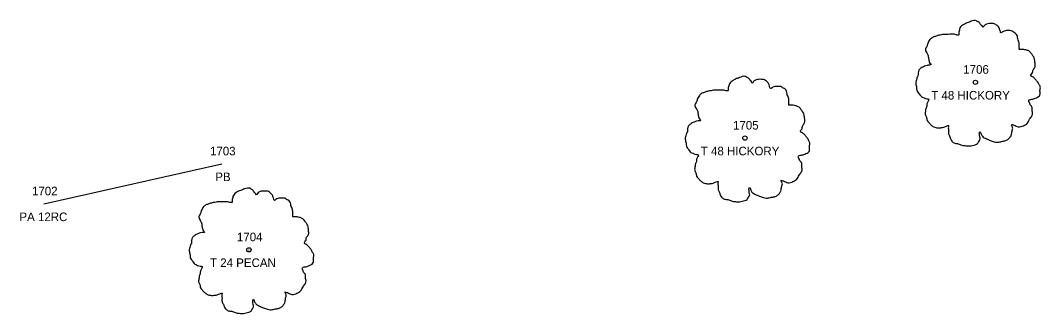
# Model space of a CAD drawing. Extents: x 1965822 to 1970313, y 1117097 to 1118160.
# Drawn here: x 1966536.2 to 1966654.8, y 1117362.7 to 1117396.8 of the extents above; entities that cross this region are included whole.
import ezdxf

# ---------------------------------------------------------------- set-up
doc = ezdxf.new("R2010")
doc.units = 0
for name, color, linetype in [('RD_EX_DR_Pipe', 7, 'Continuous'), ('RD_EX_DR_Pipe_txCode', 7, 'Continuous'), ('RD_EX_VEG', 7, 'Continuous'), ('RD_EX_VEG_txCode', 7, 'Continuous'), ('RD_SMD_Locator', 7, 'Continuous')]:
    doc.layers.add(name, color=color, linetype=linetype)

msp = doc.modelspace()

# ---------------------------------------------------------------- linework, layer by layer
at = {"layer": 'RD_EX_DR_Pipe'}
msp.add_line((1966538.93, 1117375.41), (1966559.64, 1117380.06), dxfattribs=at)
at = {"layer": 'RD_EX_VEG'}
for centre, radius in [((1966647.25, 1117389.55), 0.25), ((1966647.24, 1117389.53), 0.0001), ((1966620.45, 1117383.06), 0.25), ((1966620.44, 1117383.04), 0.0001), ((1966562.77, 1117370.07), 0.25), ((1966562.75, 1117370.05), 0.0001)]:
    msp.add_circle(centre, radius, dxfattribs=at)
for points in [[(1966647.38, 1117396.72), (1966647.08, 1117396.75), (1966646.76, 1117396.65), (1966646.51, 1117396.55), (1966646.28, 1117396.47), (1966646.06, 1117396.37), (1966645.76, 1117396.2), (1966645.53, 1117396), (1966645.41, 1117395.75), (1966645.36, 1117395.52), (1966645.31, 1117395.25), (1966645.31, 1117395.07), (1966645.18, 1117395.05), (1966645.03, 1117395.07), (1966644.78, 1117395.15), (1966644.53, 1117395.15), (1966644.28, 1117395.15), (1966643.93, 1117395.12), (1966643.58, 1117395.12), (1966643.31, 1117395.07), (1966642.98, 1117395.02), (1966642.61, 1117394.9), (1966642.26, 1117394.77), (1966641.96, 1117394.52), (1966641.71, 1117394.05), (1966641.59, 1117393.7), (1966641.44, 1117393.45), (1966641.59, 1117393), (1966641.76, 1117392.65), (1966641.79, 1117392.45), (1966641.86, 1117392.02), (1966641.96, 1117391.8), (1966642.08, 1117391.6), (1966642.01, 1117391.57), (1966641.64, 1117391.52), (1966641.34, 1117391.42), (1966640.91, 1117391.2), (1966640.69, 1117390.97), (1966640.59, 1117390.65), (1966640.56, 1117390.3), (1966640.46, 1117390.1), (1966640.39, 1117389.82), (1966640.36, 1117389.75), (1966640.31, 1117389.42), (1966640.41, 1117388.97), (1966640.44, 1117388.62), (1966640.56, 1117388.4), (1966640.71, 1117388.22), (1966640.89, 1117387.97), (1966641.29, 1117387.75), (1966641.61, 1117387.65), (1966641.81, 1117387.63), (1966641.64, 1117387.13), (1966641.59, 1117386.78), (1966641.46, 1117386.38), (1966641.46, 1117386.3), (1966641.41, 1117385.83), (1966641.56, 1117385.5), (1966641.64, 1117385.13), (1966641.81, 1117384.9), (1966642.08, 1117384.6), (1966642.41, 1117384.38), (1966642.91, 1117384.25), (1966643.31, 1117384.28), (1966643.88, 1117384.45), (1966644.13, 1117384.53), (1966644.11, 1117384.35), (1966644.13, 1117383.98), (1966644.13, 1117383.55), (1966644.28, 1117383.23), (1966644.38, 1117382.95), (1966644.53, 1117382.7), (1966644.86, 1117382.48), (1966645.26, 1117382.4), (1966645.68, 1117382.25), (1966646.13, 1117382.18), (1966646.63, 1117382.15), (1966647.23, 1117382.3), (1966647.51, 1117382.43), (1966647.61, 1117382.6), (1966647.81, 1117382.98), (1966647.76, 1117383.2), (1966647.78, 1117383.8), (1966647.88, 1117383.63), (1966648.06, 1117383.28), (1966648.56, 1117382.98), (1966648.96, 1117382.8), (1966649.43, 1117382.65), (1966649.73, 1117382.58), (1966650.21, 1117382.65), (1966650.58, 1117382.73), (1966650.96, 1117382.85), (1966651.26, 1117383.13), (1966651.43, 1117383.4), (1966651.48, 1117383.68), (1966651.56, 1117384.05), (1966651.61, 1117384.23)], [(1966651.61, 1117384.23), (1966651.53, 1117384.4), (1966651.48, 1117384.65), (1966651.56, 1117384.63), (1966651.73, 1117384.58), (1966652.01, 1117384.45), (1966652.23, 1117384.38), (1966652.56, 1117384.4), (1966652.83, 1117384.5), (1966653.28, 1117384.78), (1966653.55, 1117385.25), (1966653.83, 1117385.65), (1966653.9, 1117385.98), (1966653.85, 1117386.2), (1966653.83, 1117386.7), (1966653.63, 1117386.95), (1966653.58, 1117387.08), (1966653.48, 1117387.48), (1966653.55, 1117387.53), (1966653.83, 1117387.58), (1966654.2, 1117387.7), (1966654.48, 1117387.82), (1966654.7, 1117388), (1966654.78, 1117388.22), (1966654.75, 1117388.62), (1966654.8, 1117389.02), (1966654.73, 1117389.17), (1966654.63, 1117389.32), (1966654.55, 1117389.52), (1966654.4, 1117389.67), (1966654.3, 1117389.82), (1966654.2, 1117389.92), (1966654.08, 1117390.07), (1966653.9, 1117390.2), (1966653.75, 1117390.25), (1966653.7, 1117390.4), (1966653.85, 1117390.6), (1966653.9, 1117390.7), (1966653.93, 1117390.92), (1966654.15, 1117391.27), (1966654.2, 1117391.67), (1966654.15, 1117392.1), (1966654.1, 1117392.37), (1966653.95, 1117392.65), (1966653.75, 1117392.9), (1966653.63, 1117393.07), (1966653.45, 1117393.2), (1966653.13, 1117393.32), (1966652.88, 1117393.37), (1966652.53, 1117393.37), (1966652.33, 1117393.42), (1966652.36, 1117393.47), (1966652.36, 1117393.62), (1966652.36, 1117393.9), (1966652.28, 1117394.35), (1966652.13, 1117394.85), (1966652.13, 1117394.87), (1966652.03, 1117395.12), (1966651.81, 1117395.32), (1966651.63, 1117395.42), (1966651.43, 1117395.55), (1966651.18, 1117395.57), (1966650.88, 1117395.57), (1966650.61, 1117395.52), (1966650.41, 1117395.42), (1966650.23, 1117395.3), (1966650.16, 1117395.45), (1966650.06, 1117395.75), (1966650.01, 1117395.9), (1966649.86, 1117396.07), (1966649.63, 1117396.27), (1966649.18, 1117396.4), (1966648.56, 1117396.32), (1966648.26, 1117396.12), (1966648.11, 1117395.95), (1966648.06, 1117396.07), (1966647.86, 1117396.27), (1966647.76, 1117396.45), (1966647.58, 1117396.57), (1966647.43, 1117396.67), (1966647.33, 1117396.72)], [(1966620.59, 1117390.23), (1966620.29, 1117390.25), (1966619.96, 1117390.15), (1966619.71, 1117390.05), (1966619.49, 1117389.98), (1966619.26, 1117389.88), (1966618.96, 1117389.7), (1966618.74, 1117389.5), (1966618.61, 1117389.25), (1966618.56, 1117389.03), (1966618.51, 1117388.75), (1966618.51, 1117388.58), (1966618.39, 1117388.55), (1966618.24, 1117388.58), (1966617.99, 1117388.65), (1966617.74, 1117388.65), (1966617.49, 1117388.65), (1966617.14, 1117388.63), (1966616.79, 1117388.63), (1966616.51, 1117388.58), (1966616.19, 1117388.53), (1966615.81, 1117388.4), (1966615.46, 1117388.28), (1966615.16, 1117388.03), (1966614.91, 1117387.55), (1966614.79, 1117387.2), (1966614.64, 1117386.95), (1966614.79, 1117386.5), (1966614.96, 1117386.15), (1966614.99, 1117385.95), (1966615.06, 1117385.53), (1966615.16, 1117385.3), (1966615.29, 1117385.1), (1966615.21, 1117385.08), (1966614.84, 1117385.03), (1966614.54, 1117384.93), (1966614.11, 1117384.7), (1966613.89, 1117384.48), (1966613.79, 1117384.15), (1966613.76, 1117383.8), (1966613.66, 1117383.6), (1966613.59, 1117383.33), (1966613.56, 1117383.25), (1966613.51, 1117382.93), (1966613.61, 1117382.48), (1966613.64, 1117382.13), (1966613.76, 1117381.91), (1966613.91, 1117381.73), (1966614.09, 1117381.48), (1966614.49, 1117381.26), (1966614.81, 1117381.16), (1966615.01, 1117381.13), (1966614.84, 1117380.63), (1966614.79, 1117380.28), (1966614.66, 1117379.88), (1966614.66, 1117379.81), (1966614.61, 1117379.33), (1966614.76, 1117379.01), (1966614.84, 1117378.63), (1966615.01, 1117378.41), (1966615.29, 1117378.11), (1966615.61, 1117377.88), (1966616.11, 1117377.76), (1966616.51, 1117377.78), (1966617.09, 1117377.96), (1966617.34, 1117378.03), (1966617.31, 1117377.86), (1966617.34, 1117377.48), (1966617.34, 1117377.06), (1966617.49, 1117376.73), (1966617.59, 1117376.46), (1966617.74, 1117376.21), (1966618.06, 1117375.98), (1966618.46, 1117375.91), (1966618.89, 1117375.76), (1966619.34, 1117375.68), (1966619.84, 1117375.66), (1966620.44, 1117375.81), (1966620.71, 1117375.93), (1966620.81, 1117376.11), (1966621.01, 1117376.48), (1966620.96, 1117376.71), (1966620.99, 1117377.31), (1966621.09, 1117377.13), (1966621.26, 1117376.78), (1966621.76, 1117376.48), (1966622.16, 1117376.31), (1966622.63, 1117376.16), (1966622.93, 1117376.08), (1966623.41, 1117376.16), (1966623.78, 1117376.23), (1966624.16, 1117376.36), (1966624.46, 1117376.63), (1966624.63, 1117376.91), (1966624.68, 1117377.18), (1966624.76, 1117377.56), (1966624.81, 1117377.73)], [(1966624.81, 1117377.73), (1966624.73, 1117377.91), (1966624.68, 1117378.16), (1966624.76, 1117378.13), (1966624.93, 1117378.08), (1966625.21, 1117377.96), (1966625.43, 1117377.88), (1966625.76, 1117377.91), (1966626.03, 1117378.01), (1966626.48, 1117378.28), (1966626.76, 1117378.76), (1966627.03, 1117379.16), (1966627.11, 1117379.48), (1966627.06, 1117379.71), (1966627.03, 1117380.21), (1966626.83, 1117380.46), (1966626.78, 1117380.58), (1966626.68, 1117380.98), (1966626.76, 1117381.03), (1966627.03, 1117381.08), (1966627.41, 1117381.21), (1966627.68, 1117381.33), (1966627.91, 1117381.51), (1966627.98, 1117381.73), (1966627.96, 1117382.13), (1966628.01, 1117382.53), (1966627.93, 1117382.68), (1966627.83, 1117382.83), (1966627.76, 1117383.03), (1966627.61, 1117383.18), (1966627.51, 1117383.33), (1966627.41, 1117383.43), (1966627.28, 1117383.58), (1966627.11, 1117383.7), (1966626.96, 1117383.75), (1966626.91, 1117383.9), (1966627.06, 1117384.1), (1966627.11, 1117384.2), (1966627.13, 1117384.43), (1966627.36, 1117384.78), (1966627.41, 1117385.18), (1966627.36, 1117385.6), (1966627.31, 1117385.88), (1966627.16, 1117386.15), (1966626.96, 1117386.4), (1966626.83, 1117386.58), (1966626.66, 1117386.7), (1966626.33, 1117386.83), (1966626.08, 1117386.88), (1966625.73, 1117386.88), (1966625.53, 1117386.93), (1966625.56, 1117386.98), (1966625.56, 1117387.13), (1966625.56, 1117387.4), (1966625.48, 1117387.85), (1966625.33, 1117388.35), (1966625.33, 1117388.38), (1966625.23, 1117388.63), (1966625.01, 1117388.83), (1966624.83, 1117388.93), (1966624.63, 1117389.05), (1966624.38, 1117389.08), (1966624.08, 1117389.08), (1966623.81, 1117389.03), (1966623.61, 1117388.93), (1966623.43, 1117388.8), (1966623.36, 1117388.95), (1966623.26, 1117389.25), (1966623.21, 1117389.4), (1966623.06, 1117389.58), (1966622.83, 1117389.78), (1966622.38, 1117389.9), (1966621.76, 1117389.83), (1966621.46, 1117389.63), (1966621.31, 1117389.45), (1966621.26, 1117389.58), (1966621.06, 1117389.78), (1966620.96, 1117389.95), (1966620.79, 1117390.08), (1966620.64, 1117390.18), (1966620.54, 1117390.23)], [(1966562.9, 1117377.24), (1966562.6, 1117377.26), (1966562.27, 1117377.16), (1966562.02, 1117377.06), (1966561.8, 1117376.99), (1966561.57, 1117376.89), (1966561.27, 1117376.71), (1966561.05, 1117376.51), (1966560.92, 1117376.26), (1966560.87, 1117376.04), (1966560.82, 1117375.76), (1966560.82, 1117375.59), (1966560.7, 1117375.56), (1966560.55, 1117375.59), (1966560.3, 1117375.66), (1966560.05, 1117375.66), (1966559.8, 1117375.66), (1966559.45, 1117375.64), (1966559.1, 1117375.64), (1966558.82, 1117375.59), (1966558.5, 1117375.54), (1966558.12, 1117375.41), (1966557.77, 1117375.29), (1966557.47, 1117375.04), (1966557.22, 1117374.56), (1966557.1, 1117374.21), (1966556.95, 1117373.96), (1966557.1, 1117373.51), (1966557.27, 1117373.16), (1966557.3, 1117372.96), (1966557.37, 1117372.54), (1966557.47, 1117372.31), (1966557.6, 1117372.11), (1966557.52, 1117372.09), (1966557.15, 1117372.04), (1966556.85, 1117371.94), (1966556.43, 1117371.71), (1966556.2, 1117371.49), (1966556.1, 1117371.16), (1966556.08, 1117370.81), (1966555.98, 1117370.61), (1966555.9, 1117370.34), (1966555.88, 1117370.26), (1966555.83, 1117369.94), (1966555.93, 1117369.49), (1966555.95, 1117369.14), (1966556.08, 1117368.91), (1966556.23, 1117368.74), (1966556.4, 1117368.49), (1966556.8, 1117368.26), (1966557.12, 1117368.16), (1966557.32, 1117368.14), (1966557.15, 1117367.64), (1966557.1, 1117367.29), (1966556.98, 1117366.89), (1966556.98, 1117366.82), (1966556.93, 1117366.34), (1966557.07, 1117366.02), (1966557.15, 1117365.64), (1966557.32, 1117365.42), (1966557.6, 1117365.12), (1966557.92, 1117364.89), (1966558.42, 1117364.77), (1966558.82, 1117364.79), (1966559.4, 1117364.97), (1966559.65, 1117365.04), (1966559.62, 1117364.87), (1966559.65, 1117364.49), (1966559.65, 1117364.07), (1966559.8, 1117363.74), (1966559.9, 1117363.47), (1966560.05, 1117363.22), (1966560.37, 1117362.99), (1966560.77, 1117362.92), (1966561.2, 1117362.77), (1966561.65, 1117362.69), (1966562.15, 1117362.67), (1966562.75, 1117362.82), (1966563.02, 1117362.94), (1966563.12, 1117363.12), (1966563.32, 1117363.49), (1966563.27, 1117363.72), (1966563.3, 1117364.32), (1966563.4, 1117364.14), (1966563.57, 1117363.79), (1966564.07, 1117363.49), (1966564.47, 1117363.32), (1966564.95, 1117363.17), (1966565.25, 1117363.09), (1966565.72, 1117363.17), (1966566.1, 1117363.24), (1966566.47, 1117363.37), (1966566.77, 1117363.64), (1966566.95, 1117363.92), (1966567, 1117364.19), (1966567.07, 1117364.57), (1966567.12, 1117364.74)], [(1966567.12, 1117364.74), (1966567.05, 1117364.92), (1966567, 1117365.17), (1966567.07, 1117365.14), (1966567.25, 1117365.09), (1966567.52, 1117364.97), (1966567.75, 1117364.89), (1966568.07, 1117364.92), (1966568.35, 1117365.02), (1966568.79, 1117365.29), (1966569.07, 1117365.77), (1966569.34, 1117366.17), (1966569.42, 1117366.49), (1966569.37, 1117366.72), (1966569.34, 1117367.21), (1966569.14, 1117367.46), (1966569.09, 1117367.59), (1966568.99, 1117367.99), (1966569.07, 1117368.04), (1966569.34, 1117368.09), (1966569.72, 1117368.21), (1966569.99, 1117368.34), (1966570.22, 1117368.51), (1966570.29, 1117368.74), (1966570.27, 1117369.14), (1966570.32, 1117369.54), (1966570.24, 1117369.69), (1966570.14, 1117369.84), (1966570.07, 1117370.04), (1966569.92, 1117370.19), (1966569.82, 1117370.34), (1966569.72, 1117370.44), (1966569.59, 1117370.59), (1966569.42, 1117370.71), (1966569.27, 1117370.76), (1966569.22, 1117370.91), (1966569.37, 1117371.11), (1966569.42, 1117371.21), (1966569.44, 1117371.44), (1966569.67, 1117371.79), (1966569.72, 1117372.19), (1966569.67, 1117372.61), (1966569.62, 1117372.89), (1966569.47, 1117373.16), (1966569.27, 1117373.41), (1966569.14, 1117373.59), (1966568.97, 1117373.71), (1966568.64, 1117373.84), (1966568.4, 1117373.89), (1966568.05, 1117373.89), (1966567.85, 1117373.94), (1966567.87, 1117373.99), (1966567.87, 1117374.14), (1966567.87, 1117374.41), (1966567.8, 1117374.86), (1966567.65, 1117375.36), (1966567.65, 1117375.39), (1966567.55, 1117375.64), (1966567.32, 1117375.84), (1966567.15, 1117375.94), (1966566.95, 1117376.06), (1966566.7, 1117376.09), (1966566.4, 1117376.09), (1966566.12, 1117376.04), (1966565.92, 1117375.94), (1966565.75, 1117375.81), (1966565.67, 1117375.96), (1966565.57, 1117376.26), (1966565.52, 1117376.41), (1966565.37, 1117376.59), (1966565.15, 1117376.79), (1966564.7, 1117376.91), (1966564.07, 1117376.84), (1966563.77, 1117376.64), (1966563.62, 1117376.46), (1966563.57, 1117376.59), (1966563.37, 1117376.79), (1966563.27, 1117376.96), (1966563.1, 1117377.09), (1966562.95, 1117377.19), (1966562.85, 1117377.24)]]:
    msp.add_spline(points, degree=3, dxfattribs=at)
at = {"layer": 'RD_SMD_Locator'}
for centre in [(1966559.64, 1117380.06), (1966538.93, 1117375.41)]:
    msp.add_circle(centre, 0.001, dxfattribs=at)

# ---------------------------------------------------------------- texts
at = {"layer": 'RD_EX_DR_Pipe_txCode'}
for s, p in [('1703', (1966558.25, 1117381.06)), ('PB', (1966558.86, 1117378.06)), ('1702', (1966537.55, 1117376.41)), ('PA 12RC', (1966536.09, 1117373.41))]:
    msp.add_text(s, height=1, dxfattribs=at).set_placement(p)
at = {"layer": 'RD_EX_VEG_txCode'}
for s, p in [('1706', (1966645.84, 1117390.55)), ('T 48 HICKORY', (1966642.12, 1117387.55)), ('1705', (1966619.07, 1117384.06)), ('T 48 HICKORY', (1966615.32, 1117381.06)), ('1704', (1966561.38, 1117371.07)), ('T 24 PECAN', (1966558.25, 1117368.07))]:
    msp.add_text(s, height=1, dxfattribs=at).set_placement(p)

doc.saveas('drawing.dxf')
